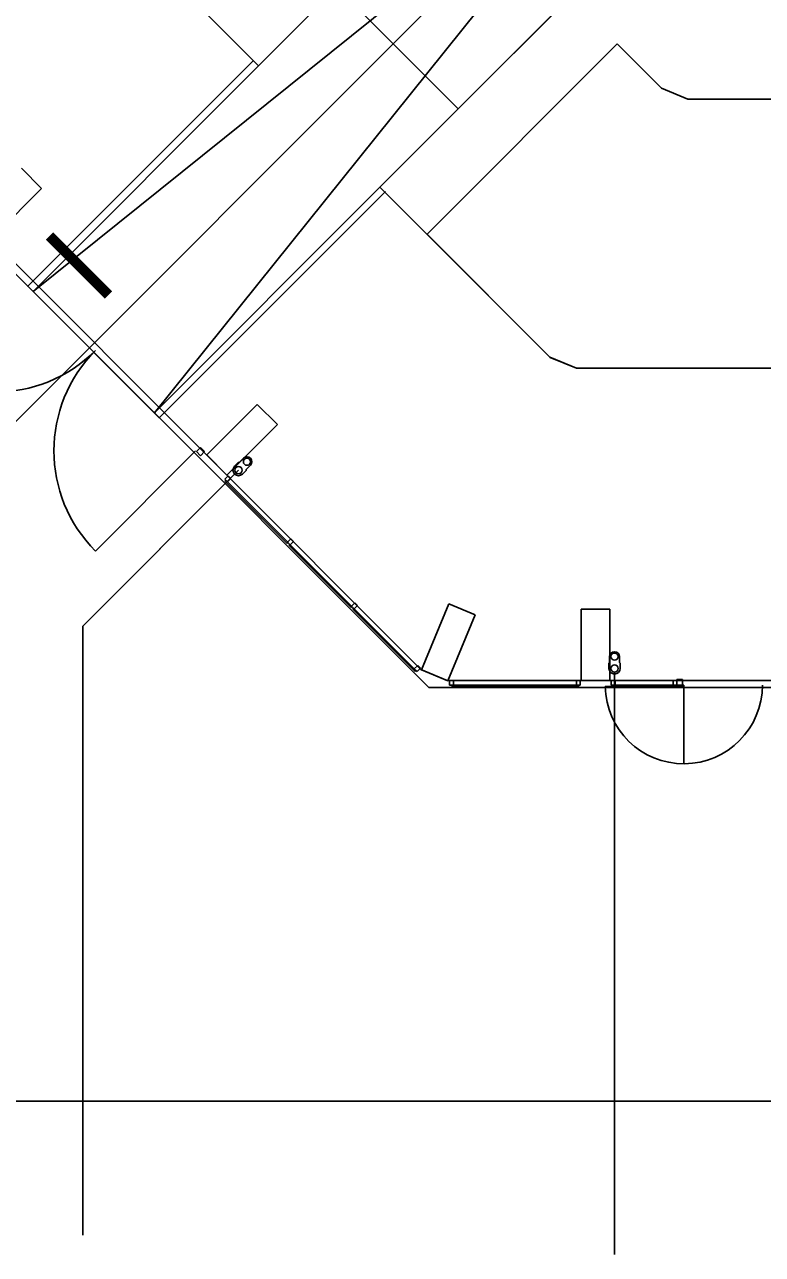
# Model space of a CAD drawing. Extents: x -264205 to -263615, y -1242401 to -1242031.
# Drawn here: x -263903.46 to -263887.96, y -1242253.35 to -1242227.54 of the extents above; entities that cross this region are included whole.
import ezdxf

# ---------------------------------------------------------------- set-up
doc = ezdxf.new("R2010")
doc.units = 0
doc.layers.add('KOORDINACNA_SITUACIA_DSP', color=7, linetype='Continuous')

msp = doc.modelspace()

# ---------------------------------------------------------------- linework, layer by layer
at = {"layer": 'KOORDINACNA_SITUACIA_DSP'}
for p, q in [((-263889.023, -1242221.253), (-263906.365, -1242238.596)), ((-263908.663, -1242227.55), (-263895.135, -1242241.078)), ((-263895.005, -1242231.945), (-263891.01, -1242227.95)), ((-263891.01, -1242227.95), (-263890.082, -1242228.878)), ((-263890.082, -1242228.878), (-263889.528, -1242229.107)), ((-263889.528, -1242229.107), (-263874.98, -1242229.107)), ((-263903.101, -1242230.985), (-263903.526, -1242230.561)), ((-263904.162, -1242232.046), (-263903.101, -1242230.985)), ((-263892.422, -1242234.528), (-263895.005, -1242231.945)), ((-263891.868, -1242234.757), (-263892.422, -1242234.528)), ((-263874.98, -1242234.757), (-263891.868, -1242234.757)), ((-263899.631, -1242236.576), (-263898.571, -1242235.516)), ((-263898.571, -1242235.516), (-263898.147, -1242235.94)), ((-263898.147, -1242235.94), (-263899.207, -1242237.001)), ((-263899.866, -1242236.488), (-263901.97, -1242238.592)), ((-263899.849, -1242236.506), (-263899.764, -1242236.421)), ((-263899.764, -1242236.591), (-263899.849, -1242236.506)), ((-263899.764, -1242236.421), (-263899.679, -1242236.506)), ((-263899.679, -1242236.506), (-263899.764, -1242236.591)), ((-263899.207, -1242237.001), (-263899.631, -1242236.576)), ((-263898.969, -1242236.733), (-263899.047, -1242236.812)), ((-263898.949, -1242236.733), (-263898.969, -1242236.733)), ((-263898.861, -1242236.645), (-263898.949, -1242236.733)), ((-263898.715, -1242236.791), (-263898.804, -1242236.879)), ((-263898.965, -1242236.895), (-263902.238, -1242240.168)), ((-263899.018, -1242236.948), (-263902.238, -1242240.168)), ((-263899.185, -1242237.014), (-263899.255, -1242237.084)), ((-263899.255, -1242237.084), (-263899.227, -1242237.113)), ((-263899.232, -1242237.108), (-263899.25, -1242237.125)), ((-263897.924, -1242238.416), (-263899.232, -1242237.108)), ((-263899.227, -1242237.113), (-263899.199, -1242237.141)), ((-263899.199, -1242237.141), (-263899.128, -1242237.07)), ((-263899.128, -1242237.07), (-263899.185, -1242237.014)), ((-263898.804, -1242236.899), (-263898.882, -1242236.977)), ((-263898.882, -1242236.977), (-263898.804, -1242236.899)), ((-263898.804, -1242236.879), (-263898.804, -1242236.899)), ((-263899.25, -1242237.125), (-263897.942, -1242238.434)), ((-263897.865, -1242238.333), (-263897.936, -1242238.404)), ((-263897.936, -1242238.404), (-263897.908, -1242238.432)), ((-263897.88, -1242238.46), (-263897.809, -1242238.389)), ((-263897.809, -1242238.389), (-263897.865, -1242238.333)), ((-263897.942, -1242238.434), (-263897.924, -1242238.416)), ((-263897.908, -1242238.432), (-263897.88, -1242238.46)), ((-263897.888, -1242238.452), (-263897.906, -1242238.469)), ((-263897.906, -1242238.469), (-263896.598, -1242239.778)), ((-263896.58, -1242239.76), (-263897.888, -1242238.452)), ((-263896.522, -1242239.677), (-263896.592, -1242239.748)), ((-263896.465, -1242239.733), (-263896.522, -1242239.677)), ((-263894.551, -1242239.702), (-263895.125, -1242241.088)), ((-263893.997, -1242239.932), (-263894.551, -1242239.702)), ((-263896.598, -1242239.778), (-263896.58, -1242239.76)), ((-263896.592, -1242239.748), (-263896.564, -1242239.776)), ((-263896.566, -1242239.809), (-263896.548, -1242239.792)), ((-263895.258, -1242241.118), (-263896.566, -1242239.809)), ((-263896.564, -1242239.776), (-263896.536, -1242239.804)), ((-263896.548, -1242239.792), (-263895.24, -1242241.1)), ((-263896.536, -1242239.804), (-263896.465, -1242239.733)), ((-263894.571, -1242241.318), (-263893.997, -1242239.932)), ((-263891.768, -1242241.312), (-263891.768, -1242239.812)), ((-263891.768, -1242239.812), (-263891.168, -1242239.812)), ((-263891.168, -1242239.812), (-263891.168, -1242241.312)), ((-263902.238, -1242240.168), (-263902.238, -1242252.949)), ((-263891.171, -1242240.932), (-263891.185, -1242240.946)), ((-263891.185, -1242240.946), (-263891.185, -1242241.057)), ((-263891.171, -1242240.807), (-263891.171, -1242240.932)), ((-263890.965, -1242240.807), (-263890.965, -1242240.932)), ((-263890.965, -1242240.932), (-263890.951, -1242240.946)), ((-263890.951, -1242241.057), (-263890.951, -1242240.946)), ((-263890.951, -1242240.946), (-263890.951, -1242241.057)), ((-263895.202, -1242240.996), (-263895.273, -1242241.067)), ((-263895.273, -1242241.067), (-263895.245, -1242241.095)), ((-263895.24, -1242241.1), (-263895.258, -1242241.118)), ((-263895.245, -1242241.095), (-263895.216, -1242241.123)), ((-263895.216, -1242241.123), (-263895.146, -1242241.053)), ((-263895.146, -1242241.053), (-263895.202, -1242240.996)), ((-263895.135, -1242241.078), (-263894.581, -1242241.307)), ((-263895.125, -1242241.088), (-263894.571, -1242241.318)), ((-263891.068, -1242241.132), (-263891.068, -1242253.353)), ((-263894.581, -1242241.307), (-263809.355, -1242241.307)), ((-263894.531, -1242241.407), (-263894.531, -1242241.307)), ((-263894.531, -1242241.307), (-263894.451, -1242241.307)), ((-263894.491, -1242241.407), (-263894.531, -1242241.407)), ((-263894.451, -1242241.407), (-263894.491, -1242241.407)), ((-263891.828, -1242241.407), (-263894.478, -1242241.407)), ((-263894.478, -1242241.407), (-263894.478, -1242241.432)), ((-263894.478, -1242241.432), (-263891.828, -1242241.432)), ((-263894.451, -1242241.307), (-263894.451, -1242241.407)), ((-263891.868, -1242241.407), (-263891.868, -1242241.307)), ((-263891.868, -1242241.307), (-263891.788, -1242241.307)), ((-263891.828, -1242241.407), (-263891.868, -1242241.407)), ((-263891.828, -1242241.432), (-263891.828, -1242241.407)), ((-263891.788, -1242241.407), (-263891.828, -1242241.407)), ((-263891.788, -1242241.307), (-263891.788, -1242241.407)), ((-263891.168, -1242241.312), (-263891.768, -1242241.312)), ((-263891.263, -1242241.432), (-263889.613, -1242241.432)), ((-263891.058, -1242241.307), (-263891.138, -1242241.307)), ((-263891.138, -1242241.307), (-263891.138, -1242241.407)), ((-263891.138, -1242241.407), (-263891.098, -1242241.407)), ((-263891.098, -1242241.432), (-263891.098, -1242241.407)), ((-263891.098, -1242241.407), (-263889.798, -1242241.407)), ((-263891.098, -1242241.407), (-263891.058, -1242241.407)), ((-263889.798, -1242241.432), (-263891.098, -1242241.432)), ((-263891.058, -1242241.407), (-263891.058, -1242241.307)), ((-263889.838, -1242241.407), (-263889.838, -1242241.307)), ((-263889.838, -1242241.307), (-263889.758, -1242241.307)), ((-263889.798, -1242241.407), (-263889.838, -1242241.407)), ((-263889.798, -1242241.407), (-263889.798, -1242241.432)), ((-263889.758, -1242241.407), (-263889.798, -1242241.407)), ((-263889.638, -1242241.287), (-263889.758, -1242241.287)), ((-263889.758, -1242241.287), (-263889.758, -1242241.407)), ((-263889.758, -1242241.307), (-263889.758, -1242241.407)), ((-263889.758, -1242241.407), (-263889.638, -1242241.407)), ((-263889.638, -1242241.407), (-263889.638, -1242241.287)), ((-263889.638, -1242241.407), (-263889.613, -1242241.407)), ((-263889.613, -1242241.407), (-263889.613, -1242243.057)), ((-263924.143, -1242250.14), (-263788.143, -1242250.14))]:
    msp.add_line(p, q, dxfattribs=at)
for points in [[(-263794.893, -1242227.382), (-263808.968, -1242241.457), (-263894.968, -1242241.457), (-263909.043, -1242227.382), (-263909.043, -1242196.333), (-263914.143, -1242196.333), (-263914.143, -1242132.433), (-263909.043, -1242132.433), (-263909.043, -1242101.382), (-263894.968, -1242087.307), (-263808.968, -1242087.307), (-263794.893, -1242101.382), (-263794.893, -1242227.382)], [(-263816.02, -1242224.432), (-263887.916, -1242224.432), (-263888.26, -1242224.088), (-263889.254, -1242226.488), (-263890.391, -1242225.351), (-263894.351, -1242229.311), (-263896.896, -1242226.765), (-263892.937, -1242222.806), (-263894.073, -1242221.669), (-263891.673, -1242220.675), (-263892.018, -1242220.33), (-263892.018, -1242181.432), (-263893.618, -1242181.432), (-263893.618, -1242147.332), (-263892.018, -1242147.332), (-263892.018, -1242108.434)], [(-263898.543, -1242228.407), (-263902.112, -1242224.837), (-263902.343, -1242224.282), (-263902.343, -1242203.332), (-263909.043, -1242203.332)], [(-263891.673, -1242220.675), (-263894.073, -1242221.669), (-263892.937, -1242222.806), (-263898.544, -1242228.407)], [(-263895.995, -1242230.956), (-263890.391, -1242225.352), (-263889.254, -1242226.488), (-263888.26, -1242224.088), (-263891.673, -1242220.675)], [(-263903.277, -1242233.148), (-263900.731, -1242235.694), (-263890.333, -1242222.748), (-263903.277, -1242233.148)], [(-263898.65, -1242228.301), (-263903.39, -1242233.035), (-263900.629, -1242235.796), (-263895.875, -1242231.049)], [(-263898.544, -1242228.407), (-263903.281, -1242233.144), (-263900.731, -1242235.694), (-263895.982, -1242230.943)], [(-263807.942, -1242230.956), (-263811.512, -1242234.526), (-263812.068, -1242234.757), (-263891.868, -1242234.757), (-263892.424, -1242234.526), (-263895.994, -1242230.956)]]:
    msp.add_lwpolyline(points, dxfattribs=at)
msp.add_lwpolyline([(-263891.01, -1242227.95), (-263895.005, -1242231.945), (-263892.422, -1242234.528), (-263891.868, -1242234.757), (-263874.98, -1242234.757), (-263874.98, -1242229.107), (-263889.528, -1242229.107), (-263890.082, -1242228.878)], close=True, dxfattribs=at)
for centre in [(-263898.965, -1242236.895), (-263898.788, -1242236.718), (-263891.068, -1242240.807), (-263891.068, -1242241.057)]:
    msp.add_circle(centre, 0.075, dxfattribs=at)
for centre, radius, start, end in [((-263904.074, -1242232.281), 2.975, 225.0001, 315.0001), ((-263899.866, -1242236.488), 2.975, 134.9999, 224.9999), ((-263898.965, -1242236.895), 0.117, 135, 315), ((-263898.788, -1242236.718), 0.103, 315, 135), ((-263891.068, -1242240.807), 0.103, 360, 180), ((-263891.068, -1242241.057), 0.117, 180, 360), ((-263889.613, -1242241.407), 1.65, 180.8682, 0)]:
    msp.add_arc(centre, radius, start, end, dxfattribs=at)

# ---------------------------------------------------------------- texts
msp.add_text('I', height=1.75, rotation=45.0119, dxfattribs=at).set_placement((-263901.924, -1242233.448))

doc.saveas('drawing.dxf')
